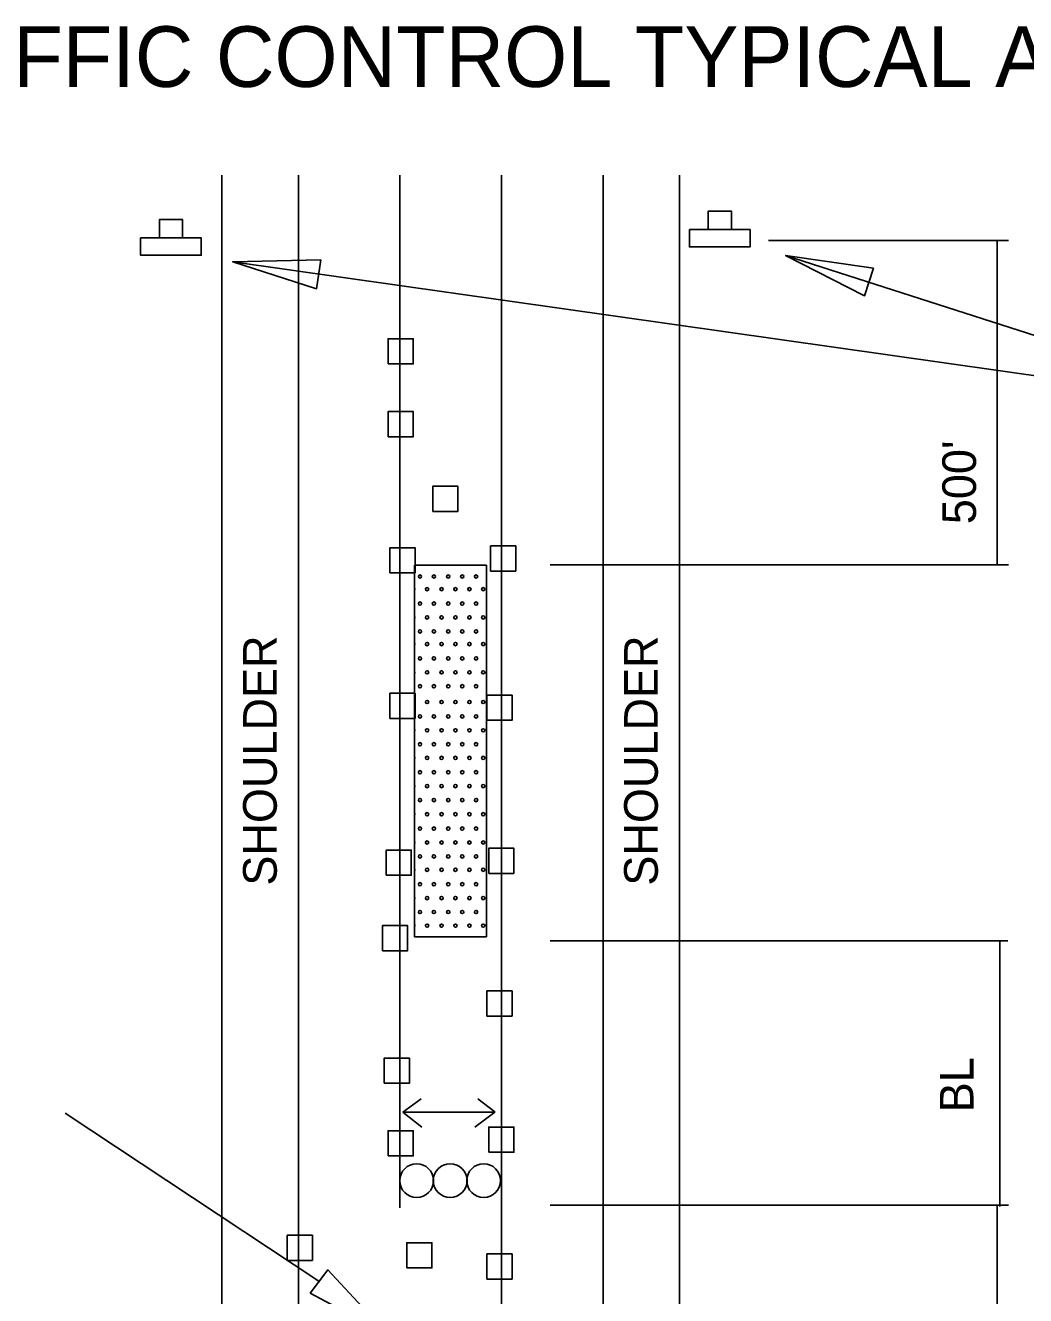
# Model space of a CAD drawing. Extents: x 1531.4 to 1538.58, y 1529.59 to 1539.33.
# Drawn here: x 1534.008 to 1535.789, y 1537.071 to 1539.335 of the extents above; entities that cross this region are included whole.
import ezdxf

# ---------------------------------------------------------------- set-up
doc = ezdxf.new("R2010")
doc.units = 0
for name, color, linetype in [('DETL-DIMS', 7, 'Continuous'), ('DETL-LINE', 7, 'Continuous'), ('DETL-NOTE', 7, 'Continuous'), ('DETL-TITL', 7, 'Continuous'), ('USER-BORD', 7, 'Continuous')]:
    doc.layers.add(name, color=color, linetype=linetype)

# ---------------------------------------------------------------- blocks, each defined once
blk = doc.blocks.new('PANEL0')
at = {"layer": 'USER-BORD'}
for centre in [(0.00309, -0.00012), (0.00928, -0.00012), (0.01546, -0.00012)]:
    blk.add_circle(centre, 0.00312, dxfattribs=at)

msp = doc.modelspace()

# ---------------------------------------------------------------- linework, layer by layer
at = {"layer": 'DETL-DIMS'}
for p, q in [((1535.3312, 1538.9514), (1535.7588, 1538.9514)), ((1535.739, 1538.9514), (1535.739, 1538.3736)), ((1535.362, 1538.9247), (1535.8708, 1538.7611)), ((1534.3772, 1538.9135), (1536.1963, 1538.6552)), ((1534.9428, 1538.3736), (1535.7588, 1538.3736)), ((1534.9428, 1537.7036), (1535.758, 1537.7036)), ((1535.7433, 1537.7036), (1535.7433, 1537.23)), ((1534.5321, 1537.0956), (1534.0784, 1537.3962)), ((1534.9428, 1537.2326), (1535.7588, 1537.2326)), ((1535.739, 1536.7864), (1535.739, 1537.2326))]:
    msp.add_line(p, q, dxfattribs=at)
for points in [[(1535.5183, 1538.9021), (1535.5025, 1538.8529), (1535.362, 1538.9247)], [(1534.5339, 1538.917), (1534.5262, 1538.8653), (1534.3772, 1538.9135)], [(1534.5148, 1537.0758), (1534.5467, 1537.1172), (1534.6535, 1537.0018)]]:
    msp.add_lwpolyline(points, close=True, dxfattribs=at)
at = {"layer": 'DETL-LINE'}
for p, q in [((1534.3579, 1539.0677), (1534.3579, 1532.0386)), ((1534.4942, 1539.0677), (1534.4942, 1532.8569)), ((1534.675, 1539.0677), (1534.675, 1537.2274)), ((1534.8559, 1539.0677), (1534.8559, 1532.8233)), ((1535.0367, 1539.0677), (1535.0367, 1532.8569)), ((1535.173, 1539.0677), (1535.173, 1532.0854)), ((1534.8292, 1538.3728), (1534.7009, 1538.3728)), ((1534.7009, 1538.3728), (1534.7009, 1537.7105)), ((1534.8292, 1538.3728), (1534.7009, 1538.3728)), ((1534.7009, 1538.3728), (1534.7009, 1537.7105)), ((1534.8292, 1537.7105), (1534.8292, 1538.3728)), ((1534.8292, 1537.7105), (1534.8292, 1538.3728)), ((1534.7106, 1538.3526), (1534.7106, 1538.3526)), ((1534.7106, 1538.3526), (1534.7106, 1538.3526)), ((1534.7354, 1538.3526), (1534.7354, 1538.3526)), ((1534.7354, 1538.3526), (1534.7354, 1538.3526)), ((1534.761, 1538.3526), (1534.761, 1538.3526)), ((1534.761, 1538.3526), (1534.761, 1538.3526)), ((1534.7858, 1538.3526), (1534.7858, 1538.3526)), ((1534.7858, 1538.3526), (1534.7858, 1538.3526)), ((1534.8106, 1538.3526), (1534.8106, 1538.3526)), ((1534.8106, 1538.3526), (1534.8106, 1538.3526)), ((1534.7234, 1538.33), (1534.7234, 1538.33)), ((1534.7234, 1538.33), (1534.7234, 1538.33)), ((1534.7482, 1538.33), (1534.7482, 1538.33)), ((1534.749, 1538.33), (1534.749, 1538.33)), ((1534.773, 1538.33), (1534.773, 1538.33)), ((1534.7738, 1538.33), (1534.7738, 1538.33)), ((1534.7978, 1538.33), (1534.7978, 1538.33)), ((1534.7986, 1538.33), (1534.7986, 1538.33)), ((1534.8234, 1538.33), (1534.8234, 1538.33)), ((1534.8234, 1538.33), (1534.8234, 1538.33)), ((1534.7106, 1538.3044), (1534.7106, 1538.3044)), ((1534.7354, 1538.3044), (1534.7354, 1538.3044)), ((1534.761, 1538.3044), (1534.761, 1538.3044)), ((1534.7858, 1538.3044), (1534.7858, 1538.3044)), ((1534.8106, 1538.3044), (1534.8106, 1538.3044)), ((1534.4942, 1538.2728), (1534.4942, 1532.062)), ((1534.7234, 1538.2796), (1534.7234, 1538.2796)), ((1534.7234, 1538.2796), (1534.7234, 1538.2796)), ((1534.7482, 1538.2796), (1534.7482, 1538.2796)), ((1534.749, 1538.2796), (1534.749, 1538.2796)), ((1534.773, 1538.2796), (1534.773, 1538.2796)), ((1534.7738, 1538.2796), (1534.7738, 1538.2796)), ((1534.7978, 1538.2796), (1534.7978, 1538.2796)), ((1534.7986, 1538.2796), (1534.7986, 1538.2796)), ((1534.8234, 1538.2796), (1534.8234, 1538.2796)), ((1534.8234, 1538.2796), (1534.8234, 1538.2796)), ((1535.0367, 1538.2728), (1535.0367, 1532.062)), ((1535.173, 1538.2844), (1535.173, 1532.2515)), ((1535.173, 1538.2728), (1535.173, 1532.0386)), ((1534.4942, 1538.261), (1534.4942, 1532.0502)), ((1534.4942, 1538.2494), (1534.4942, 1532.0386)), ((1534.7106, 1538.2548), (1534.7106, 1538.2548)), ((1534.7106, 1538.2548), (1534.7106, 1538.2548)), ((1534.7354, 1538.2548), (1534.7354, 1538.2548)), ((1534.7354, 1538.2548), (1534.7354, 1538.2548)), ((1534.761, 1538.2548), (1534.761, 1538.2548)), ((1534.761, 1538.2548), (1534.761, 1538.2548)), ((1534.7858, 1538.2548), (1534.7858, 1538.2548)), ((1534.7858, 1538.2548), (1534.7858, 1538.2548)), ((1534.8106, 1538.2548), (1534.8106, 1538.2548)), ((1534.8106, 1538.2548), (1534.8106, 1538.2548)), ((1534.8559, 1538.261), (1534.8559, 1532.0166)), ((1535.0367, 1538.261), (1535.0367, 1532.0502)), ((1535.0367, 1538.2494), (1535.0367, 1532.0386)), ((1534.7234, 1538.2322), (1534.7234, 1538.2322)), ((1534.7234, 1538.2322), (1534.7234, 1538.2322)), ((1534.7482, 1538.2322), (1534.7482, 1538.2322)), ((1534.749, 1538.2322), (1534.749, 1538.2322)), ((1534.773, 1538.2322), (1534.773, 1538.2322)), ((1534.7738, 1538.2322), (1534.7738, 1538.2322)), ((1534.7978, 1538.2322), (1534.7978, 1538.2322)), ((1534.7986, 1538.2322), (1534.7986, 1538.2322)), ((1534.8234, 1538.2322), (1534.8234, 1538.2322)), ((1534.8234, 1538.2322), (1534.8234, 1538.2322)), ((1534.7106, 1538.2066), (1534.7106, 1538.2066)), ((1534.7354, 1538.2066), (1534.7354, 1538.2066)), ((1534.761, 1538.2066), (1534.761, 1538.2066)), ((1534.7858, 1538.2066), (1534.7858, 1538.2066)), ((1534.8106, 1538.2066), (1534.8106, 1538.2066)), ((1534.7234, 1538.1818), (1534.7234, 1538.1818)), ((1534.7234, 1538.1818), (1534.7234, 1538.1818)), ((1534.7482, 1538.1818), (1534.7482, 1538.1818)), ((1534.749, 1538.1818), (1534.749, 1538.1818)), ((1534.773, 1538.1818), (1534.773, 1538.1818)), ((1534.7738, 1538.1818), (1534.7738, 1538.1818)), ((1534.7978, 1538.1818), (1534.7978, 1538.1818)), ((1534.7986, 1538.1818), (1534.7986, 1538.1818)), ((1534.8234, 1538.1818), (1534.8234, 1538.1818)), ((1534.8234, 1538.1818), (1534.8234, 1538.1818)), ((1534.7106, 1538.157), (1534.7106, 1538.157)), ((1534.7106, 1538.157), (1534.7106, 1538.157)), ((1534.7354, 1538.157), (1534.7354, 1538.157)), ((1534.7354, 1538.157), (1534.7354, 1538.157)), ((1534.761, 1538.157), (1534.761, 1538.157)), ((1534.761, 1538.157), (1534.761, 1538.157)), ((1534.7858, 1538.157), (1534.7858, 1538.157)), ((1534.7858, 1538.157), (1534.7858, 1538.157)), ((1534.8106, 1538.157), (1534.8106, 1538.157)), ((1534.8106, 1538.157), (1534.8106, 1538.157)), ((1534.7234, 1538.129), (1534.7234, 1538.129)), ((1534.7234, 1538.129), (1534.7234, 1538.129)), ((1534.7482, 1538.129), (1534.7482, 1538.129)), ((1534.749, 1538.129), (1534.749, 1538.129)), ((1534.773, 1538.129), (1534.773, 1538.129)), ((1534.7738, 1538.129), (1534.7738, 1538.129)), ((1534.7978, 1538.129), (1534.7978, 1538.129)), ((1534.7986, 1538.129), (1534.7986, 1538.129)), ((1534.8234, 1538.129), (1534.8234, 1538.129)), ((1534.8234, 1538.129), (1534.8234, 1538.129)), ((1534.7106, 1538.1034), (1534.7106, 1538.1034)), ((1534.7354, 1538.1034), (1534.7354, 1538.1034)), ((1534.761, 1538.1034), (1534.761, 1538.1034)), ((1534.7858, 1538.1034), (1534.7858, 1538.1034)), ((1534.8106, 1538.1034), (1534.8106, 1538.1034)), ((1534.7234, 1538.0786), (1534.7234, 1538.0786)), ((1534.7234, 1538.0786), (1534.7234, 1538.0786)), ((1534.7482, 1538.0786), (1534.7482, 1538.0786)), ((1534.749, 1538.0786), (1534.749, 1538.0786)), ((1534.773, 1538.0786), (1534.773, 1538.0786)), ((1534.7738, 1538.0786), (1534.7738, 1538.0786)), ((1534.7978, 1538.0786), (1534.7978, 1538.0786)), ((1534.7986, 1538.0786), (1534.7986, 1538.0786)), ((1534.8234, 1538.0786), (1534.8234, 1538.0786)), ((1534.8234, 1538.0786), (1534.8234, 1538.0786)), ((1534.7106, 1538.0538), (1534.7106, 1538.0538)), ((1534.7106, 1538.0538), (1534.7106, 1538.0538)), ((1534.7354, 1538.0538), (1534.7354, 1538.0538)), ((1534.7354, 1538.0538), (1534.7354, 1538.0538)), ((1534.761, 1538.0538), (1534.761, 1538.0538)), ((1534.761, 1538.0538), (1534.761, 1538.0538)), ((1534.7858, 1538.0538), (1534.7858, 1538.0538)), ((1534.7858, 1538.0538), (1534.7858, 1538.0538)), ((1534.8106, 1538.0538), (1534.8106, 1538.0538)), ((1534.8106, 1538.0538), (1534.8106, 1538.0538)), ((1534.7234, 1538.0295), (1534.7234, 1538.0295)), ((1534.7234, 1538.0295), (1534.7234, 1538.0295)), ((1534.7482, 1538.0295), (1534.7482, 1538.0295)), ((1534.749, 1538.0295), (1534.749, 1538.0295)), ((1534.773, 1538.0295), (1534.773, 1538.0295)), ((1534.7738, 1538.0295), (1534.7738, 1538.0295)), ((1534.7978, 1538.0295), (1534.7978, 1538.0295)), ((1534.7986, 1538.0295), (1534.7986, 1538.0295)), ((1534.8234, 1538.0295), (1534.8234, 1538.0295)), ((1534.8234, 1538.0295), (1534.8234, 1538.0295)), ((1534.7106, 1538.0039), (1534.7106, 1538.0039)), ((1534.7354, 1538.0039), (1534.7354, 1538.0039)), ((1534.761, 1538.0039), (1534.761, 1538.0039)), ((1534.7858, 1538.0039), (1534.7858, 1538.0039)), ((1534.8106, 1538.0039), (1534.8106, 1538.0039)), ((1534.7234, 1537.9791), (1534.7234, 1537.9791)), ((1534.7234, 1537.9791), (1534.7234, 1537.9791)), ((1534.7482, 1537.9791), (1534.7482, 1537.9791)), ((1534.749, 1537.9791), (1534.749, 1537.9791)), ((1534.773, 1537.9791), (1534.773, 1537.9791)), ((1534.7738, 1537.9791), (1534.7738, 1537.9791)), ((1534.7978, 1537.9791), (1534.7978, 1537.9791)), ((1534.7986, 1537.9791), (1534.7986, 1537.9791)), ((1534.8234, 1537.9791), (1534.8234, 1537.9791)), ((1534.8234, 1537.9791), (1534.8234, 1537.9791)), ((1534.7106, 1537.9543), (1534.7106, 1537.9543)), ((1534.7106, 1537.9543), (1534.7106, 1537.9543)), ((1534.7354, 1537.9543), (1534.7354, 1537.9543)), ((1534.7354, 1537.9543), (1534.7354, 1537.9543)), ((1534.761, 1537.9543), (1534.761, 1537.9543)), ((1534.761, 1537.9543), (1534.761, 1537.9543)), ((1534.7858, 1537.9543), (1534.7858, 1537.9543)), ((1534.7858, 1537.9543), (1534.7858, 1537.9543)), ((1534.8106, 1537.9543), (1534.8106, 1537.9543)), ((1534.8106, 1537.9543), (1534.8106, 1537.9543)), ((1534.7234, 1537.929), (1534.7234, 1537.929)), ((1534.7234, 1537.929), (1534.7234, 1537.929)), ((1534.7482, 1537.929), (1534.7482, 1537.929)), ((1534.749, 1537.929), (1534.749, 1537.929)), ((1534.773, 1537.929), (1534.773, 1537.929)), ((1534.7738, 1537.929), (1534.7738, 1537.929)), ((1534.7978, 1537.929), (1534.7978, 1537.929)), ((1534.7986, 1537.929), (1534.7986, 1537.929)), ((1534.8234, 1537.929), (1534.8234, 1537.929)), ((1534.8234, 1537.929), (1534.8234, 1537.929)), ((1534.7106, 1537.9034), (1534.7106, 1537.9034)), ((1534.7354, 1537.9034), (1534.7354, 1537.9034)), ((1534.761, 1537.9034), (1534.761, 1537.9034)), ((1534.7858, 1537.9034), (1534.7858, 1537.9034)), ((1534.8106, 1537.9034), (1534.8106, 1537.9034)), ((1534.7234, 1537.8786), (1534.7234, 1537.8786)), ((1534.7234, 1537.8786), (1534.7234, 1537.8786)), ((1534.7482, 1537.8786), (1534.7482, 1537.8786)), ((1534.749, 1537.8786), (1534.749, 1537.8786)), ((1534.773, 1537.8786), (1534.773, 1537.8786)), ((1534.7738, 1537.8786), (1534.7738, 1537.8786)), ((1534.7978, 1537.8786), (1534.7978, 1537.8786)), ((1534.7986, 1537.8786), (1534.7986, 1537.8786)), ((1534.8234, 1537.8786), (1534.8234, 1537.8786)), ((1534.8234, 1537.8786), (1534.8234, 1537.8786)), ((1534.7106, 1537.8538), (1534.7106, 1537.8538)), ((1534.7106, 1537.8538), (1534.7106, 1537.8538)), ((1534.7354, 1537.8538), (1534.7354, 1537.8538)), ((1534.7354, 1537.8538), (1534.7354, 1537.8538)), ((1534.761, 1537.8538), (1534.761, 1537.8538)), ((1534.761, 1537.8538), (1534.761, 1537.8538)), ((1534.7858, 1537.8538), (1534.7858, 1537.8538)), ((1534.7858, 1537.8538), (1534.7858, 1537.8538)), ((1534.8106, 1537.8538), (1534.8106, 1537.8538)), ((1534.8106, 1537.8538), (1534.8106, 1537.8538)), ((1534.7234, 1537.83), (1534.7234, 1537.83)), ((1534.7234, 1537.83), (1534.7234, 1537.83)), ((1534.7482, 1537.83), (1534.7482, 1537.83)), ((1534.749, 1537.83), (1534.749, 1537.83)), ((1534.773, 1537.83), (1534.773, 1537.83)), ((1534.7738, 1537.83), (1534.7738, 1537.83)), ((1534.7978, 1537.83), (1534.7978, 1537.83)), ((1534.7986, 1537.83), (1534.7986, 1537.83)), ((1534.8234, 1537.83), (1534.8234, 1537.83)), ((1534.8234, 1537.83), (1534.8234, 1537.83)), ((1534.7106, 1537.8044), (1534.7106, 1537.8044)), ((1534.7354, 1537.8044), (1534.7354, 1537.8044)), ((1534.761, 1537.8044), (1534.761, 1537.8044)), ((1534.7858, 1537.8044), (1534.7858, 1537.8044)), ((1534.8106, 1537.8044), (1534.8106, 1537.8044)), ((1534.7234, 1537.7796), (1534.7234, 1537.7796)), ((1534.7234, 1537.7796), (1534.7234, 1537.7796)), ((1534.7482, 1537.7796), (1534.7482, 1537.7796)), ((1534.749, 1537.7796), (1534.749, 1537.7796)), ((1534.773, 1537.7796), (1534.773, 1537.7796)), ((1534.7738, 1537.7796), (1534.7738, 1537.7796)), ((1534.7978, 1537.7796), (1534.7978, 1537.7796)), ((1534.7986, 1537.7796), (1534.7986, 1537.7796)), ((1534.8234, 1537.7796), (1534.8234, 1537.7796)), ((1534.8234, 1537.7796), (1534.8234, 1537.7796)), ((1534.7106, 1537.7548), (1534.7106, 1537.7548)), ((1534.7106, 1537.7548), (1534.7106, 1537.7548)), ((1534.7354, 1537.7548), (1534.7354, 1537.7548)), ((1534.7354, 1537.7548), (1534.7354, 1537.7548)), ((1534.761, 1537.7548), (1534.761, 1537.7548)), ((1534.761, 1537.7548), (1534.761, 1537.7548)), ((1534.7858, 1537.7548), (1534.7858, 1537.7548)), ((1534.7858, 1537.7548), (1534.7858, 1537.7548)), ((1534.8106, 1537.7548), (1534.8106, 1537.7548)), ((1534.8106, 1537.7548), (1534.8106, 1537.7548)), ((1534.7234, 1537.7304), (1534.7234, 1537.7304)), ((1534.7234, 1537.7304), (1534.7234, 1537.7304)), ((1534.7482, 1537.7304), (1534.7482, 1537.7304)), ((1534.749, 1537.7304), (1534.749, 1537.7304)), ((1534.773, 1537.7304), (1534.773, 1537.7304)), ((1534.7738, 1537.7304), (1534.7738, 1537.7304)), ((1534.7978, 1537.7304), (1534.7978, 1537.7304)), ((1534.7986, 1537.7304), (1534.7986, 1537.7304)), ((1534.8234, 1537.7304), (1534.8234, 1537.7304)), ((1534.8234, 1537.7304), (1534.8234, 1537.7304)), ((1534.7009, 1537.7105), (1534.8292, 1537.7105)), ((1534.7009, 1537.7105), (1534.8292, 1537.7105)), ((1534.6802, 1537.3979), (1534.7129, 1537.422)), ((1534.8438, 1537.3988), (1534.8137, 1537.422)), ((1534.6802, 1537.3979), (1534.7138, 1537.3712)), ((1534.6811, 1537.3979), (1534.8447, 1537.3979)), ((1534.8438, 1537.3979), (1534.8085, 1537.3712))]:
    msp.add_line(p, q, dxfattribs=at)
for points in [[(1535.2241, 1538.9708), (1535.2654, 1538.9708), (1535.2654, 1539.0036), (1535.2241, 1539.0036)], [(1534.2465, 1538.956), (1534.2878, 1538.956), (1534.2878, 1538.9887), (1534.2465, 1538.9887)], [(1535.1905, 1538.9708), (1535.1905, 1538.94), (1535.2987, 1538.94), (1535.2987, 1538.9708)], [(1534.2129, 1538.956), (1534.2129, 1538.9251), (1534.3211, 1538.9251), (1534.3211, 1538.956)], [(1534.6537, 1538.7314), (1534.6985, 1538.7314), (1534.6985, 1538.7762), (1534.6537, 1538.7762)], [(1534.6537, 1538.6017), (1534.6985, 1538.6017), (1534.6985, 1538.6465), (1534.6537, 1538.6465)], [(1534.7335, 1538.4687), (1534.7783, 1538.4687), (1534.7783, 1538.5135), (1534.7335, 1538.5135)], [(1534.6571, 1538.359), (1534.7019, 1538.359), (1534.7019, 1538.4038), (1534.6571, 1538.4038)], [(1534.8365, 1538.3623), (1534.8813, 1538.3623), (1534.8813, 1538.4071), (1534.8365, 1538.4071)], [(1534.6571, 1538.0996), (1534.7019, 1538.0996), (1534.7019, 1538.1444), (1534.6571, 1538.1444)], [(1534.8298, 1538.0963), (1534.8746, 1538.0963), (1534.8746, 1538.1411), (1534.8298, 1538.1411)], [(1534.6504, 1537.8203), (1534.6952, 1537.8203), (1534.6952, 1537.8651), (1534.6504, 1537.8651)], [(1534.8331, 1537.8236), (1534.8779, 1537.8236), (1534.8779, 1537.8684), (1534.8331, 1537.8684)], [(1534.6438, 1537.6858), (1534.6886, 1537.6858), (1534.6886, 1537.7306), (1534.6438, 1537.7306)], [(1534.8298, 1537.5694), (1534.8746, 1537.5694), (1534.8746, 1537.6142), (1534.8298, 1537.6142)], [(1534.6471, 1537.4497), (1534.6919, 1537.4497), (1534.6919, 1537.4945), (1534.6471, 1537.4945)], [(1534.6537, 1537.32), (1534.6985, 1537.32), (1534.6985, 1537.3648), (1534.6537, 1537.3648)], [(1534.8331, 1537.3267), (1534.8779, 1537.3267), (1534.8779, 1537.3715), (1534.8331, 1537.3715)], [(1534.4743, 1537.1338), (1534.5191, 1537.1338), (1534.5191, 1537.1786), (1534.4743, 1537.1786)], [(1534.687, 1537.1205), (1534.7318, 1537.1205), (1534.7318, 1537.1653), (1534.687, 1537.1653)], [(1534.8298, 1537.1006), (1534.8746, 1537.1006), (1534.8746, 1537.1454), (1534.8298, 1537.1454)]]:
    msp.add_lwpolyline(points, close=True, dxfattribs=at)
for points in [[(1534.675, 1538.8877), (1534.675, 1538.7677)], [(1534.8559, 1538.8877), (1534.8559, 1538.7677)], [(1534.675, 1538.4077), (1534.675, 1538.2877)], [(1534.8559, 1538.4077), (1534.8559, 1538.2877)], [(1534.7009, 1538.3318), (1534.7009, 1538.3282)], [(1534.7009, 1538.2814), (1534.7009, 1538.2778)], [(1534.7009, 1538.234), (1534.7009, 1538.2304)], [(1534.7009, 1538.1836), (1534.7009, 1538.18)], [(1534.7009, 1538.1307), (1534.7009, 1538.1271)], [(1534.7009, 1538.0803), (1534.7009, 1538.0767)], [(1534.7009, 1538.0312), (1534.7009, 1538.0276)], [(1534.7009, 1537.9808), (1534.7009, 1537.9772)], [(1534.675, 1537.9277), (1534.675, 1537.8077)], [(1534.7009, 1537.9308), (1534.7009, 1537.9272)], [(1534.8559, 1537.9277), (1534.8559, 1537.8077)], [(1534.7009, 1537.8804), (1534.7009, 1537.8768)], [(1534.7009, 1537.8317), (1534.7009, 1537.8281)], [(1534.7009, 1537.7813), (1534.7009, 1537.7777)], [(1534.7009, 1537.7322), (1534.7009, 1537.7286)], [(1534.675, 1537.4477), (1534.675, 1537.3277)], [(1534.8559, 1537.4477), (1534.8559, 1537.3277)]]:
    msp.add_lwpolyline(points, dxfattribs=at)
for centre in [(1534.7106, 1538.3526), (1534.7354, 1538.3526), (1534.761, 1538.3526), (1534.7858, 1538.3526), (1534.8106, 1538.3526), (1534.7234, 1538.33), (1534.749, 1538.33), (1534.7738, 1538.33), (1534.7986, 1538.33), (1534.8234, 1538.33), (1534.7106, 1538.3044), (1534.7354, 1538.3044), (1534.761, 1538.3044), (1534.7858, 1538.3044), (1534.8106, 1538.3044), (1534.7234, 1538.2796), (1534.749, 1538.2796), (1534.7738, 1538.2796), (1534.7986, 1538.2796), (1534.8234, 1538.2796), (1534.7106, 1538.2548), (1534.7354, 1538.2548), (1534.761, 1538.2548), (1534.7858, 1538.2548), (1534.8106, 1538.2548), (1534.7234, 1538.2322), (1534.749, 1538.2322), (1534.7738, 1538.2322), (1534.7986, 1538.2322), (1534.8234, 1538.2322), (1534.7106, 1538.2066), (1534.7354, 1538.2066), (1534.761, 1538.2066), (1534.7858, 1538.2066), (1534.8106, 1538.2066), (1534.7234, 1538.1818), (1534.749, 1538.1818), (1534.7738, 1538.1818), (1534.7986, 1538.1818), (1534.8234, 1538.1818), (1534.7106, 1538.157), (1534.7354, 1538.157), (1534.761, 1538.157), (1534.7858, 1538.157), (1534.8106, 1538.157), (1534.7234, 1538.1289), (1534.749, 1538.1289), (1534.7738, 1538.1289), (1534.7986, 1538.1289), (1534.8234, 1538.1289), (1534.7106, 1538.1033), (1534.7354, 1538.1033), (1534.761, 1538.1033), (1534.7858, 1538.1033), (1534.8106, 1538.1033), (1534.7234, 1538.0785), (1534.749, 1538.0785), (1534.7738, 1538.0785), (1534.7986, 1538.0785), (1534.8234, 1538.0785), (1534.7106, 1538.0537), (1534.7354, 1538.0537), (1534.761, 1538.0537), (1534.7858, 1538.0537), (1534.8106, 1538.0537), (1534.7234, 1538.0294), (1534.749, 1538.0294), (1534.7738, 1538.0294), (1534.7986, 1538.0294), (1534.8234, 1538.0294), (1534.7106, 1538.0038), (1534.7354, 1538.0038), (1534.761, 1538.0038), (1534.7858, 1538.0038), (1534.8106, 1538.0038), (1534.7234, 1537.979), (1534.749, 1537.979), (1534.7738, 1537.979), (1534.7986, 1537.979), (1534.8234, 1537.979), (1534.7106, 1537.9542), (1534.7354, 1537.9542), (1534.761, 1537.9542), (1534.7858, 1537.9542), (1534.8106, 1537.9542), (1534.7234, 1537.929), (1534.749, 1537.929), (1534.7738, 1537.929), (1534.7986, 1537.929), (1534.8234, 1537.929), (1534.7106, 1537.9034), (1534.7354, 1537.9034), (1534.761, 1537.9034), (1534.7858, 1537.9034), (1534.8106, 1537.9034), (1534.7234, 1537.8786), (1534.749, 1537.8786), (1534.7738, 1537.8786), (1534.7986, 1537.8786), (1534.8234, 1537.8786), (1534.7106, 1537.8538), (1534.7354, 1537.8538), (1534.761, 1537.8538), (1534.7858, 1537.8538), (1534.8106, 1537.8538), (1534.7234, 1537.8299), (1534.749, 1537.8299), (1534.7738, 1537.8299), (1534.7986, 1537.8299), (1534.8234, 1537.8299), (1534.7106, 1537.8043), (1534.7354, 1537.8043), (1534.761, 1537.8043), (1534.7858, 1537.8043), (1534.8106, 1537.8043), (1534.7234, 1537.7795), (1534.749, 1537.7795), (1534.7738, 1537.7795), (1534.7986, 1537.7795), (1534.8234, 1537.7795), (1534.7106, 1537.7547), (1534.7354, 1537.7547), (1534.761, 1537.7547), (1534.7858, 1537.7547), (1534.8106, 1537.7547), (1534.7234, 1537.7304), (1534.749, 1537.7304), (1534.7738, 1537.7304), (1534.7986, 1537.7304), (1534.8234, 1537.7304)]:
    msp.add_circle(centre, 0.00291, dxfattribs=at)
for centre in [(1534.6986, 1538.33), (1534.6986, 1538.2796), (1534.6986, 1538.2322), (1534.6986, 1538.1818), (1534.6986, 1538.1289), (1534.6986, 1538.0785), (1534.6986, 1538.0294), (1534.6986, 1537.979), (1534.6986, 1537.929), (1534.6986, 1537.8786), (1534.6986, 1537.8299), (1534.6986, 1537.7795), (1534.6986, 1537.7304)]:
    msp.add_arc(centre, 0.00291, 321.9078, 38.0922, dxfattribs=at)

# ---------------------------------------------------------------- block references
at = {"layer": 'DETL-LINE', "xscale": 9.645601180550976, "yscale": 9.645601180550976}
msp.add_blockref('PANEL0', (1534.6749, 1537.2772), dxfattribs=at)

# ---------------------------------------------------------------- texts
at = {"layer": 'DETL-NOTE'}
for s, p in [("500'", (1535.7011, 1538.4458)), ('SHOULDER', (1534.4555, 1537.8017)), ('SHOULDER', (1535.1343, 1537.8017)), ('BL', (1535.6967, 1537.3978))]:
    msp.add_text(s, height=0.06, rotation=90, dxfattribs=at).set_placement(p)
at = {"layer": 'DETL-TITL'}
msp.add_text('TEMPORARY TRAFFIC CONTROL TYPICAL APPLICATION', height=0.108, dxfattribs=at).set_placement((1532.7424, 1539.225))

doc.saveas('drawing.dxf')
